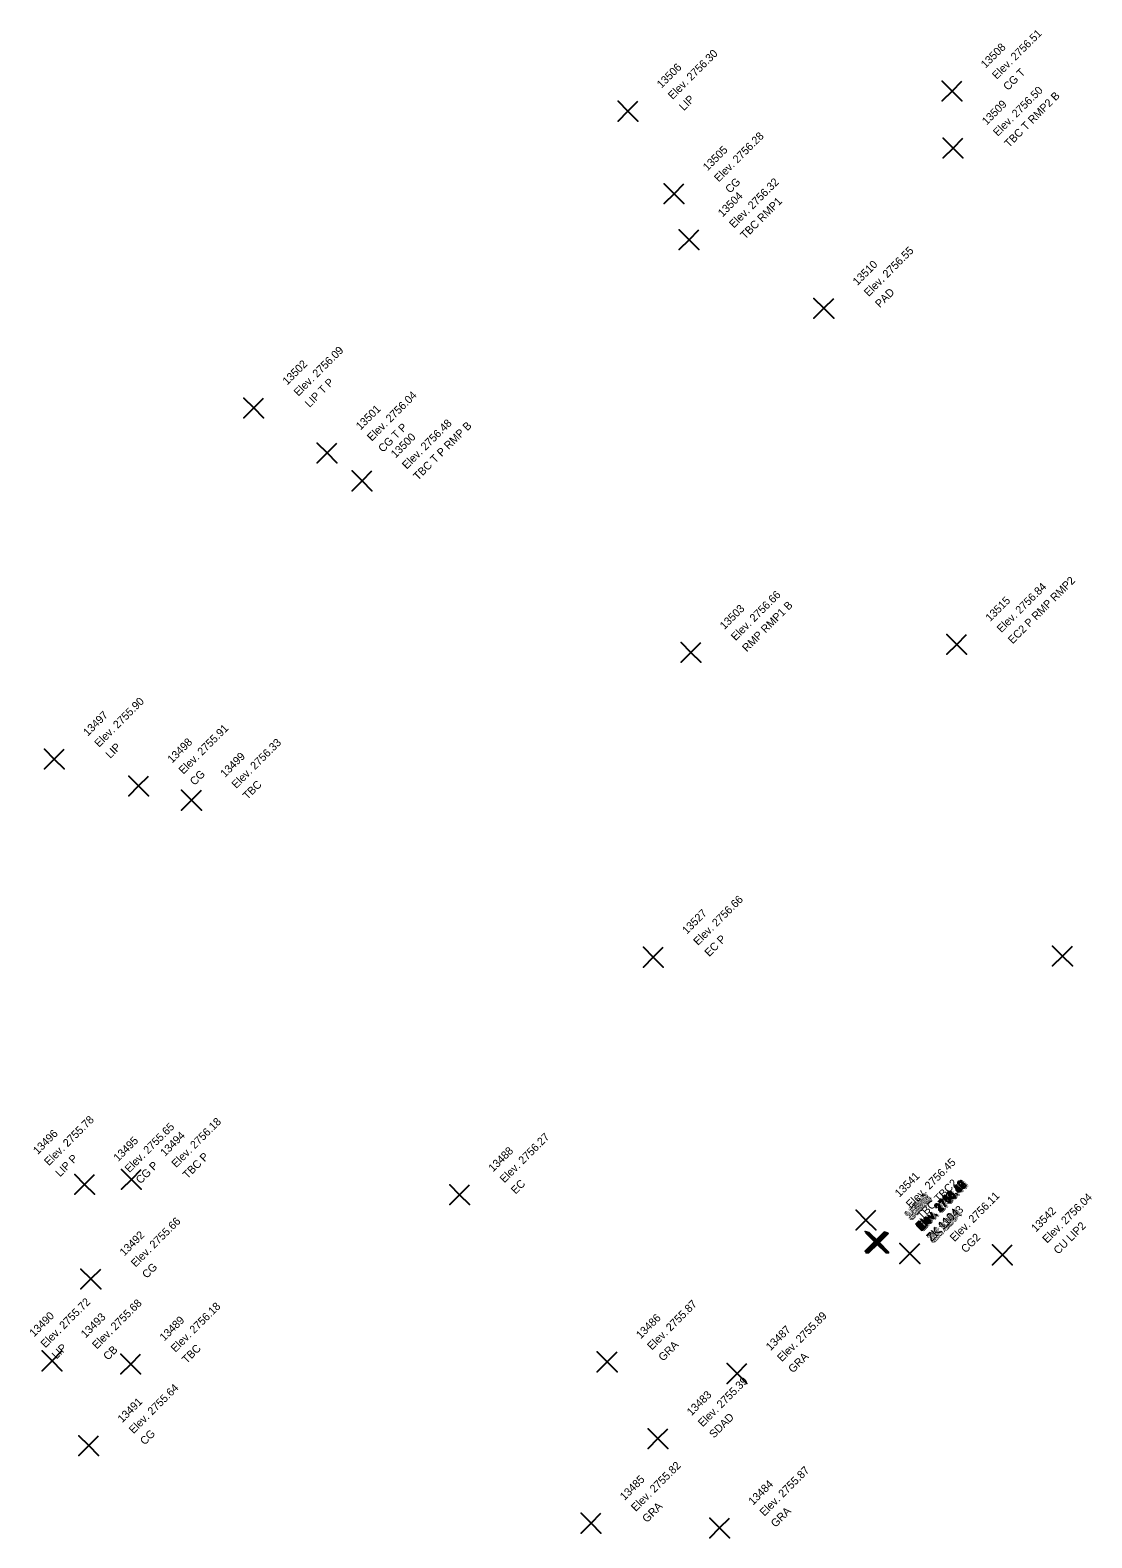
# Model space of a CAD drawing. Extents: x 2493999 to 2503109, y 700767 to 706646.
# Drawn here: x 2502319.85 to 2502335.97, y 703160.38 to 703183.26 of the extents above; entities that cross this region are included whole.
import ezdxf

# ---------------------------------------------------------------- set-up
doc = ezdxf.new("R2010")
doc.units = 0
doc.layers.add('ALG_CL_BLUE_Horiz', color=7, linetype='Continuous')
doc.layers.add('DES_SURFACE_Existing-Ground', color=7, linetype='Continuous')

msp = doc.modelspace()

# ---------------------------------------------------------------- linework, layer by layer
at = {"layer": 'ALG_CL_BLUE_Horiz'}
for points in [[(2502333.847, 703182.332), (2502333.697, 703182.482), (2502333.847, 703182.332), (2502333.697, 703182.182), (2502333.847, 703182.332), (2502333.997, 703182.182), (2502333.847, 703182.332), (2502333.997, 703182.482)], [(2502328.928, 703182.027), (2502328.778, 703182.177), (2502328.928, 703182.027), (2502328.778, 703181.877), (2502328.928, 703182.027), (2502329.078, 703181.877), (2502328.928, 703182.027), (2502329.078, 703182.177)], [(2502333.863, 703181.468), (2502333.713, 703181.618), (2502333.863, 703181.468), (2502333.713, 703181.318), (2502333.863, 703181.468), (2502334.013, 703181.318), (2502333.863, 703181.468), (2502334.013, 703181.618)], [(2502329.628, 703180.774), (2502329.478, 703180.924), (2502329.628, 703180.774), (2502329.478, 703180.624), (2502329.628, 703180.774), (2502329.778, 703180.624), (2502329.628, 703180.774), (2502329.778, 703180.924)], [(2502329.856, 703180.076), (2502329.706, 703180.226), (2502329.856, 703180.076), (2502329.706, 703179.926), (2502329.856, 703180.076), (2502330.006, 703179.926), (2502329.856, 703180.076), (2502330.006, 703180.226)], [(2502331.902, 703179.036), (2502331.752, 703179.186), (2502331.902, 703179.036), (2502331.752, 703178.886), (2502331.902, 703179.036), (2502332.052, 703178.886), (2502331.902, 703179.036), (2502332.052, 703179.186)], [(2502323.248, 703177.524), (2502323.098, 703177.674), (2502323.248, 703177.524), (2502323.098, 703177.374), (2502323.248, 703177.524), (2502323.398, 703177.374), (2502323.248, 703177.524), (2502323.398, 703177.674)], [(2502324.361, 703176.842), (2502324.211, 703176.992), (2502324.361, 703176.842), (2502324.211, 703176.692), (2502324.361, 703176.842), (2502324.511, 703176.692), (2502324.361, 703176.842), (2502324.511, 703176.992)], [(2502324.892, 703176.418), (2502324.742, 703176.568), (2502324.892, 703176.418), (2502324.742, 703176.268), (2502324.892, 703176.418), (2502325.042, 703176.268), (2502324.892, 703176.418), (2502325.042, 703176.568)], [(2502329.884, 703173.815), (2502329.734, 703173.965), (2502329.884, 703173.815), (2502329.734, 703173.665), (2502329.884, 703173.815), (2502330.034, 703173.665), (2502329.884, 703173.815), (2502330.034, 703173.965)], [(2502333.918, 703173.937), (2502333.768, 703174.087), (2502333.918, 703173.937), (2502333.768, 703173.787), (2502333.918, 703173.937), (2502334.068, 703173.787), (2502333.918, 703173.937), (2502334.068, 703174.087)], [(2502320.222, 703172.198), (2502320.072, 703172.348), (2502320.222, 703172.198), (2502320.072, 703172.048), (2502320.222, 703172.198), (2502320.372, 703172.048), (2502320.222, 703172.198), (2502320.372, 703172.348)], [(2502321.502, 703171.789), (2502321.352, 703171.939), (2502321.502, 703171.789), (2502321.352, 703171.639), (2502321.502, 703171.789), (2502321.652, 703171.639), (2502321.502, 703171.789), (2502321.652, 703171.939)], [(2502322.304, 703171.573), (2502322.154, 703171.723), (2502322.304, 703171.573), (2502322.154, 703171.423), (2502322.304, 703171.573), (2502322.454, 703171.423), (2502322.304, 703171.573), (2502322.454, 703171.723)], [(2502329.313, 703169.192), (2502329.163, 703169.342), (2502329.313, 703169.192), (2502329.163, 703169.042), (2502329.313, 703169.192), (2502329.463, 703169.042), (2502329.313, 703169.192), (2502329.463, 703169.342)], [(2502335.524, 703169.209), (2502335.374, 703169.359), (2502335.524, 703169.209), (2502335.374, 703169.059), (2502335.524, 703169.209), (2502335.674, 703169.059), (2502335.524, 703169.209), (2502335.674, 703169.359)], [(2502320.682, 703165.744), (2502320.532, 703165.894), (2502320.682, 703165.744), (2502320.532, 703165.594), (2502320.682, 703165.744), (2502320.832, 703165.594), (2502320.682, 703165.744), (2502320.832, 703165.894)], [(2502321.392, 703165.821), (2502321.242, 703165.971), (2502321.392, 703165.821), (2502321.242, 703165.671), (2502321.392, 703165.821), (2502321.542, 703165.671), (2502321.392, 703165.821), (2502321.542, 703165.971)], [(2502326.374, 703165.588), (2502326.224, 703165.738), (2502326.374, 703165.588), (2502326.224, 703165.438), (2502326.374, 703165.588), (2502326.524, 703165.438), (2502326.374, 703165.588), (2502326.524, 703165.738)], [(2502332.541, 703165.204), (2502332.391, 703165.354), (2502332.541, 703165.204), (2502332.391, 703165.054), (2502332.541, 703165.204), (2502332.691, 703165.054), (2502332.541, 703165.204), (2502332.691, 703165.354)], [(2502332.678, 703164.879), (2502332.528, 703165.029), (2502332.678, 703164.879), (2502332.528, 703164.729), (2502332.678, 703164.879), (2502332.828, 703164.729), (2502332.678, 703164.879), (2502332.828, 703165.029)], [(2502332.687, 703164.873), (2502332.537, 703165.023), (2502332.687, 703164.873), (2502332.537, 703164.723), (2502332.687, 703164.873), (2502332.837, 703164.723), (2502332.687, 703164.873), (2502332.837, 703165.023)], [(2502332.691, 703164.873), (2502332.541, 703165.023), (2502332.691, 703164.873), (2502332.541, 703164.723), (2502332.691, 703164.873), (2502332.841, 703164.723), (2502332.691, 703164.873), (2502332.841, 703165.023)], [(2502332.696, 703164.854), (2502332.546, 703165.004), (2502332.696, 703164.854), (2502332.546, 703164.704), (2502332.696, 703164.854), (2502332.846, 703164.704), (2502332.696, 703164.854), (2502332.846, 703165.004)], [(2502332.701, 703164.876), (2502332.551, 703165.026), (2502332.701, 703164.876), (2502332.551, 703164.726), (2502332.701, 703164.876), (2502332.851, 703164.726), (2502332.701, 703164.876), (2502332.851, 703165.026)], [(2502332.704, 703164.868), (2502332.554, 703165.018), (2502332.704, 703164.868), (2502332.554, 703164.718), (2502332.704, 703164.868), (2502332.854, 703164.718), (2502332.704, 703164.868), (2502332.854, 703165.018)], [(2502332.709, 703164.867), (2502332.559, 703165.017), (2502332.709, 703164.867), (2502332.559, 703164.717), (2502332.709, 703164.867), (2502332.859, 703164.717), (2502332.709, 703164.867), (2502332.859, 703165.017)], [(2502332.709, 703164.855), (2502332.559, 703165.005), (2502332.709, 703164.855), (2502332.559, 703164.705), (2502332.709, 703164.855), (2502332.859, 703164.705), (2502332.709, 703164.855), (2502332.859, 703165.005)], [(2502332.711, 703164.868), (2502332.561, 703165.018), (2502332.711, 703164.868), (2502332.561, 703164.718), (2502332.711, 703164.868), (2502332.861, 703164.718), (2502332.711, 703164.868), (2502332.861, 703165.018)], [(2502332.715, 703164.87), (2502332.565, 703165.02), (2502332.715, 703164.87), (2502332.565, 703164.72), (2502332.715, 703164.87), (2502332.865, 703164.72), (2502332.715, 703164.87), (2502332.865, 703165.02)], [(2502332.718, 703164.857), (2502332.568, 703165.007), (2502332.718, 703164.857), (2502332.568, 703164.707), (2502332.718, 703164.857), (2502332.868, 703164.707), (2502332.718, 703164.857), (2502332.868, 703165.007)], [(2502332.727, 703164.865), (2502332.577, 703165.015), (2502332.727, 703164.865), (2502332.577, 703164.715), (2502332.727, 703164.865), (2502332.877, 703164.715), (2502332.727, 703164.865), (2502332.877, 703165.015)], [(2502332.728, 703164.861), (2502332.578, 703165.011), (2502332.728, 703164.861), (2502332.578, 703164.711), (2502332.728, 703164.861), (2502332.878, 703164.711), (2502332.728, 703164.861), (2502332.878, 703165.011)], [(2502332.73, 703164.867), (2502332.58, 703165.017), (2502332.73, 703164.867), (2502332.58, 703164.717), (2502332.73, 703164.867), (2502332.88, 703164.717), (2502332.73, 703164.867), (2502332.88, 703165.017)], [(2502332.731, 703164.854), (2502332.581, 703165.004), (2502332.731, 703164.854), (2502332.581, 703164.704), (2502332.731, 703164.854), (2502332.881, 703164.704), (2502332.731, 703164.854), (2502332.881, 703165.004)], [(2502332.735, 703164.866), (2502332.585, 703165.016), (2502332.735, 703164.866), (2502332.585, 703164.716), (2502332.735, 703164.866), (2502332.885, 703164.716), (2502332.735, 703164.866), (2502332.885, 703165.016)], [(2502333.206, 703164.696), (2502333.056, 703164.846), (2502333.206, 703164.696), (2502333.056, 703164.546), (2502333.206, 703164.696), (2502333.356, 703164.546), (2502333.206, 703164.696), (2502333.356, 703164.846)], [(2502334.611, 703164.675), (2502334.461, 703164.825), (2502334.611, 703164.675), (2502334.461, 703164.525), (2502334.611, 703164.675), (2502334.761, 703164.525), (2502334.611, 703164.675), (2502334.761, 703164.825)], [(2502320.776, 703164.31), (2502320.626, 703164.46), (2502320.776, 703164.31), (2502320.626, 703164.16), (2502320.776, 703164.31), (2502320.926, 703164.16), (2502320.776, 703164.31), (2502320.926, 703164.46)], [(2502320.187, 703163.068), (2502320.037, 703163.218), (2502320.187, 703163.068), (2502320.037, 703162.918), (2502320.187, 703163.068), (2502320.337, 703162.918), (2502320.187, 703163.068), (2502320.337, 703163.218)], [(2502321.382, 703163.019), (2502321.232, 703163.169), (2502321.382, 703163.019), (2502321.232, 703162.869), (2502321.382, 703163.019), (2502321.532, 703162.869), (2502321.382, 703163.019), (2502321.532, 703163.169)], [(2502328.613, 703163.053), (2502328.463, 703163.203), (2502328.613, 703163.053), (2502328.463, 703162.903), (2502328.613, 703163.053), (2502328.763, 703162.903), (2502328.613, 703163.053), (2502328.763, 703163.203)], [(2502330.584, 703162.876), (2502330.434, 703163.026), (2502330.584, 703162.876), (2502330.434, 703162.726), (2502330.584, 703162.876), (2502330.734, 703162.726), (2502330.584, 703162.876), (2502330.734, 703163.026)], [(2502329.384, 703161.887), (2502329.234, 703162.037), (2502329.384, 703161.887), (2502329.234, 703161.737), (2502329.384, 703161.887), (2502329.534, 703161.737), (2502329.384, 703161.887), (2502329.534, 703162.037)], [(2502320.745, 703161.782), (2502320.595, 703161.932), (2502320.745, 703161.782), (2502320.595, 703161.632), (2502320.745, 703161.782), (2502320.895, 703161.632), (2502320.745, 703161.782), (2502320.895, 703161.932)], [(2502328.368, 703160.604), (2502328.218, 703160.754), (2502328.368, 703160.604), (2502328.218, 703160.454), (2502328.368, 703160.604), (2502328.518, 703160.454), (2502328.368, 703160.604), (2502328.518, 703160.754)], [(2502330.319, 703160.532), (2502330.169, 703160.682), (2502330.319, 703160.532), (2502330.169, 703160.382), (2502330.319, 703160.532), (2502330.469, 703160.382), (2502330.319, 703160.532), (2502330.469, 703160.682)]]:
    msp.add_lwpolyline(points, dxfattribs=at)

# ---------------------------------------------------------------- texts
at = {"layer": 'DES_SURFACE_Existing-Ground'}
for s, p in [('13508', (2502334.356, 703182.671)), ('Elev. 2756.51', (2502334.526, 703182.502)), ('Elev. 2756.30', (2502329.607, 703182.197)), ('13506', (2502329.437, 703182.366)), ('CG T', (2502334.696, 703182.332)), ('Elev. 2756.50', (2502334.542, 703181.638)), ('LIP', (2502329.777, 703182.027)), ('13509', (2502334.372, 703181.807)), ('TBC T RMP2 B', (2502334.712, 703181.468)), ('Elev. 2756.28', (2502330.307, 703180.944)), ('13505', (2502330.137, 703181.113)), ('CG', (2502330.477, 703180.774)), ('Elev. 2756.32', (2502330.535, 703180.246)), ('13504', (2502330.365, 703180.415)), ('TBC RMP1', (2502330.705, 703180.076)), ('Elev. 2756.55', (2502332.581, 703179.206)), ('13510', (2502332.411, 703179.375)), ('PAD', (2502332.751, 703179.036)), ('13502', (2502323.757, 703177.863)), ('Elev. 2756.09', (2502323.927, 703177.694)), ('LIP T P', (2502324.097, 703177.524)), ('13501', (2502324.87, 703177.181)), ('Elev. 2756.04', (2502325.04, 703177.012)), ('Elev. 2756.48', (2502325.571, 703176.588)), ('CG T P', (2502325.21, 703176.842)), ('13500', (2502325.401, 703176.757)), ('TBC T P RMP B', (2502325.741, 703176.418)), ('Elev. 2756.84', (2502334.597, 703174.107)), ('EC2 P RMP RMP2', (2502334.767, 703173.937)), ('Elev. 2756.66', (2502330.563, 703173.985)), ('RMP RMP1 B', (2502330.733, 703173.815)), ('13515', (2502334.427, 703174.276)), ('13503', (2502330.393, 703174.154)), ('Elev. 2755.90', (2502320.901, 703172.368)), ('13497', (2502320.731, 703172.537)), ('Elev. 2755.91', (2502322.181, 703171.959)), ('LIP', (2502321.071, 703172.198)), ('13498', (2502322.011, 703172.128)), ('13499', (2502322.813, 703171.912)), ('Elev. 2756.33', (2502322.983, 703171.743)), ('CG', (2502322.351, 703171.789)), ('TBC', (2502323.153, 703171.573)), ('Elev. 2756.66', (2502329.992, 703169.362)), ('13527', (2502329.822, 703169.531)), ('EC P', (2502330.162, 703169.192)), ('13496', (2502319.97, 703166.189)), ('Elev. 2755.78', (2502320.14, 703166.02)), ('Elev. 2755.65', (2502321.361, 703165.914)), ('Elev. 2756.18', (2502322.071, 703165.991)), ('13495', (2502321.191, 703166.083)), ('13494', (2502321.901, 703166.16)), ('Elev. 2756.27', (2502327.053, 703165.758)), ('LIP P', (2502320.31, 703165.85)), ('TBC P', (2502322.241, 703165.821)), ('13488', (2502326.883, 703165.927)), ('Elev. 2756.45', (2502333.22, 703165.374)), ('CG P', (2502321.531, 703165.744)), ('13541', (2502333.05, 703165.543)), ('EC', (2502327.223, 703165.588)), ('Elev. 2756.49', (2502333.357, 703165.049)), ('Elev. 2756.49', (2502333.366, 703165.043)), ('Elev. 2756.47', (2502333.37, 703165.043)), ('Elev. 2756.49', (2502333.375, 703165.024)), ('Elev. 2756.47', (2502333.38, 703165.046)), ('TBC TBC2', (2502333.39, 703165.204)), ('Elev. 2756.52', (2502333.383, 703165.038)), ('Elev. 2756.50', (2502333.388, 703165.037)), ('Elev. 2756.48', (2502333.388, 703165.025)), ('Elev. 2756.51', (2502333.39, 703165.038)), ('Elev. 2756.47', (2502333.394, 703165.04)), ('Elev. 2756.48', (2502333.397, 703165.027)), ('Elev. 2756.50', (2502333.406, 703165.035)), ('Elev. 2756.51', (2502333.407, 703165.031)), ('Elev. 2756.46', (2502333.409, 703165.037)), ('Elev. 2756.47', (2502333.41, 703165.024)), ('Elev. 2756.48', (2502333.414, 703165.036)), ('11735', (2502333.187, 703165.218)), ('13135', (2502333.196, 703165.212)), ('11734', (2502333.2, 703165.212)), ('14161', (2502333.205, 703165.193)), ('12317', (2502333.21, 703165.215)), ('13546', (2502333.213, 703165.207)), ('13136', (2502333.218, 703165.206)), ('12322', (2502333.218, 703165.194)), ('16953', (2502333.22, 703165.207)), ('18357', (2502333.224, 703165.209)), ('15627', (2502333.227, 703165.196)), ('14183', (2502333.236, 703165.204)), ('1104', (2502333.237, 703165.2)), ('15626', (2502333.239, 703165.206)), ('10002', (2502333.24, 703165.193)), ('10064', (2502333.244, 703165.205)), ('Elev. 2756.11', (2502333.885, 703164.866)), ('Elev. 2756.04', (2502335.29, 703164.845)), ('Elev. 2755.66', (2502321.455, 703164.48)), ('ZK 1104', (2502333.527, 703164.879)), ('ZK 1104', (2502333.536, 703164.873)), ('ZK 1104', (2502333.54, 703164.873)), ('ZK 1104', (2502333.545, 703164.854)), ('ZK 1104', (2502333.55, 703164.876)), ('ZK 1104', (2502333.553, 703164.868)), ('ZK 1104', (2502333.558, 703164.867)), ('ZK 1104', (2502333.558, 703164.855)), ('ZK 1104', (2502333.56, 703164.868)), ('ZK 1104', (2502333.564, 703164.87)), ('ZK 1104', (2502333.567, 703164.857)), ('ZK 1104', (2502333.576, 703164.865)), ('ZK 1104', (2502333.579, 703164.867)), ('ZK 1104', (2502333.58, 703164.854)), ('ZK 1104', (2502333.584, 703164.866)), ('13543', (2502333.715, 703165.035)), ('13542', (2502335.12, 703165.014)), ('13492', (2502321.285, 703164.649)), ('XSX', (2502333.577, 703164.861)), ('CG2', (2502334.055, 703164.696)), ('CU LIP2', (2502335.46, 703164.675)), ('CG', (2502321.625, 703164.31)), ('Elev. 2755.72', (2502320.085, 703163.255)), ('Elev. 2755.68', (2502320.866, 703163.238)), ('Elev. 2756.18', (2502322.061, 703163.189)), ('Elev. 2755.87', (2502329.292, 703163.223)), ('13490', (2502319.915, 703163.424)), ('13493', (2502320.696, 703163.407)), ('13489', (2502321.891, 703163.358)), ('13486', (2502329.122, 703163.392)), ('13487', (2502331.093, 703163.215)), ('Elev. 2755.89', (2502331.263, 703163.046)), ('LIP', (2502320.255, 703163.085)), ('CB', (2502321.036, 703163.068)), ('TBC', (2502322.231, 703163.019)), ('GRA', (2502329.462, 703163.053)), ('GRA', (2502331.433, 703162.876)), ('Elev. 2755.64', (2502321.424, 703161.952)), ('Elev. 2755.39', (2502330.063, 703162.057)), ('13491', (2502321.254, 703162.121)), ('13483', (2502329.893, 703162.226)), ('SDAD', (2502330.233, 703161.887)), ('CG', (2502321.594, 703161.782)), ('13485', (2502328.877, 703160.943)), ('Elev. 2755.82', (2502329.047, 703160.774)), ('Elev. 2755.87', (2502330.998, 703160.702)), ('13484', (2502330.828, 703160.871)), ('GRA', (2502329.217, 703160.604)), ('GRA', (2502331.168, 703160.532))]:
    msp.add_text(s, height=0.12, rotation=45, dxfattribs=at).set_placement(p)

doc.saveas('drawing.dxf')
